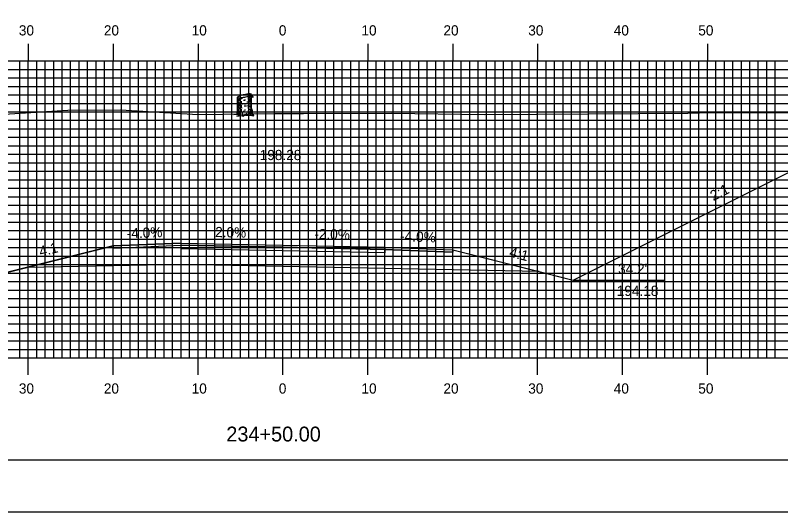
# Model space of a CAD drawing. Extents: x 1800355 to 1800699, y 442591 to 442811.
# Drawn here: x 1800489.5 to 1800579.7, y 442590.5 to 442649 of the extents above; entities that cross this region are included whole.
import ezdxf

# ---------------------------------------------------------------- set-up
doc = ezdxf.new("R2010")
doc.units = 0
for name, color, linetype in [('ANNOTATION', 7, 'Continuous'), ('BORDER', 7, 'Continuous'), ('D_Roadway_Centerline', 7, 'Continuous'), ('D_Roadway_Centerline_Text', 7, 'Continuous'), ('D_Roadway_Edge_Shoulder', 7, 'Continuous'), ('D_Roadway_Edge_TW', 7, 'Continuous'), ('D_Roadway_Pavement', 7, 'Continuous'), ('D_Roadway_SlopeLines', 7, 'Continuous'), ('D_Roadway_SubGrade', 7, 'Continuous'), ('H_V ANNOTATION', 7, 'Continuous'), ('MAJOR', 7, 'Continuous'), ('MINOR', 7, 'Continuous'), ('PDRAIN', 7, 'Continuous'), ('PLOT BOUNDARY', 7, 'Continuous'), ('S_Roadway_Centerline', 7, 'Continuous'), ('S_Trees_Conifer_Pay', 7, 'Continuous')]:
    doc.layers.add(name, color=color, linetype=linetype)

msp = doc.modelspace()

# ---------------------------------------------------------------- linework, layer by layer
at = {"layer": 'BORDER'}
msp.add_lwpolyline([(1800371.436, 442596.665), (1800691.436, 442596.665), (1800691.436, 442806.665), (1800371.436, 442806.665)], close=True, dxfattribs=at)
at = {"layer": 'D_Roadway_Centerline'}
msp.add_lwpolyline([(1800446.785, 442637.108), (1800448.035, 442637.032), (1800449.285, 442636.8), (1800450.535, 442636.41), (1800451.785, 442635.864), (1800486.862, 442618.325), (1800490.862, 442619.325), (1800501.036, 442621.869), (1800509.036, 442622.189), (1800521.036, 442621.949), (1800533.036, 442621.709), (1800541.036, 442621.389), (1800551.21, 442618.845), (1800555.21, 442617.845), (1800591.968, 442636.224), (1800593.218, 442636.77), (1800594.468, 442637.156), (1800595.718, 442637.383), (1800596.968, 442637.451)], dxfattribs=at)
at = {"layer": 'D_Roadway_Edge_Shoulder'}
for points in [[(1800509.036, 442622.189), (1800501.036, 442621.869), (1800501.036, 442621.619), (1800509.036, 442621.939)], [(1800533.036, 442621.709), (1800541.036, 442621.389), (1800541.036, 442621.139), (1800533.036, 442621.459)]]:
    msp.add_lwpolyline(points, close=True, dxfattribs=at)
at = {"layer": 'D_Roadway_Edge_TW'}
msp.add_lwpolyline([(1800509.036, 442621.939), (1800509.036, 442622.189), (1800521.036, 442621.949), (1800533.036, 442621.709), (1800533.036, 442621.459), (1800521.036, 442621.699)], close=True, dxfattribs=at)
at = {"layer": 'D_Roadway_Pavement'}
msp.add_lwpolyline([(1800509.036, 442621.522), (1800509.036, 442621.939), (1800521.036, 442621.699), (1800533.036, 442621.459), (1800533.036, 442621.042), (1800521.036, 442621.282)], close=True, dxfattribs=at)
at = {"layer": 'D_Roadway_SlopeLines'}
for points in [[(1800555.21, 442617.845), (1800591.968, 442636.224), (1800593.218, 442636.77), (1800594.468, 442637.156), (1800595.718, 442637.383), (1800596.968, 442637.451)], [(1800501.036, 442621.869), (1800486.862, 442618.325)], [(1800541.036, 442621.389), (1800555.21, 442617.845)]]:
    msp.add_lwpolyline(points, dxfattribs=at)
at = {"layer": 'D_Roadway_SubGrade'}
msp.add_lwpolyline([(1800509.036, 442619.689), (1800490.862, 442619.325), (1800501.036, 442621.869), (1800501.036, 442621.619), (1800509.036, 442621.939), (1800521.036, 442621.699), (1800533.036, 442621.459), (1800541.036, 442621.139), (1800541.036, 442621.389), (1800551.21, 442618.845), (1800533.036, 442619.209), (1800521.036, 442619.449)], close=True, dxfattribs=at)
at = {"layer": 'MAJOR'}
for p, q in [((1800491.036, 442645.669), (1800491.036, 442643.665)), ((1800501.036, 442645.669), (1800501.036, 442643.665)), ((1800511.036, 442645.669), (1800511.036, 442643.665)), ((1800521.036, 442645.669), (1800521.036, 442643.665)), ((1800531.036, 442645.669), (1800531.036, 442643.665)), ((1800541.036, 442645.669), (1800541.036, 442643.665)), ((1800551.036, 442645.669), (1800551.036, 442643.665)), ((1800561.036, 442645.669), (1800561.036, 442643.665)), ((1800571.036, 442645.669), (1800571.036, 442643.665)), ((1800381.036, 442643.665), (1800661.036, 442643.665)), ((1800381.036, 442643.665), (1800661.036, 442643.665)), ((1800491.036, 442608.665), (1800491.036, 442643.665)), ((1800501.036, 442608.665), (1800501.036, 442643.665)), ((1800511.036, 442608.665), (1800511.036, 442643.665)), ((1800521.036, 442608.665), (1800521.036, 442643.665)), ((1800531.036, 442608.665), (1800531.036, 442643.665)), ((1800541.036, 442608.665), (1800541.036, 442643.665)), ((1800551.036, 442608.665), (1800551.036, 442643.665)), ((1800561.036, 442608.665), (1800561.036, 442643.665)), ((1800571.036, 442608.665), (1800571.036, 442643.665)), ((1800381.036, 442638.665), (1800661.036, 442638.665)), ((1800381.036, 442633.665), (1800661.036, 442633.665)), ((1800381.036, 442628.665), (1800661.036, 442628.665)), ((1800381.036, 442623.665), (1800661.036, 442623.665)), ((1800381.036, 442618.665), (1800661.036, 442618.665)), ((1800381.036, 442613.665), (1800661.036, 442613.665)), ((1800381.036, 442608.665), (1800661.036, 442608.665)), ((1800381.036, 442608.665), (1800661.036, 442608.665)), ((1800491.036, 442606.661), (1800491.036, 442608.665)), ((1800501.036, 442606.661), (1800501.036, 442608.665)), ((1800511.036, 442606.661), (1800511.036, 442608.665)), ((1800521.036, 442606.661), (1800521.036, 442608.665)), ((1800531.036, 442606.661), (1800531.036, 442608.665)), ((1800541.036, 442606.661), (1800541.036, 442608.665)), ((1800551.036, 442606.661), (1800551.036, 442608.665)), ((1800561.036, 442606.661), (1800561.036, 442608.665)), ((1800571.036, 442606.661), (1800571.036, 442608.665))]:
    msp.add_line(p, q, dxfattribs=at)
at = {"layer": 'MINOR'}
for p, q in [((1800490.036, 442608.665), (1800490.036, 442643.665)), ((1800492.036, 442608.665), (1800492.036, 442643.665)), ((1800493.036, 442608.665), (1800493.036, 442643.665)), ((1800494.036, 442608.665), (1800494.036, 442643.665)), ((1800495.036, 442608.665), (1800495.036, 442643.665)), ((1800496.036, 442608.665), (1800496.036, 442643.665)), ((1800497.036, 442608.665), (1800497.036, 442643.665)), ((1800498.036, 442608.665), (1800498.036, 442643.665)), ((1800499.036, 442608.665), (1800499.036, 442643.665)), ((1800500.036, 442608.665), (1800500.036, 442643.665)), ((1800502.036, 442608.665), (1800502.036, 442643.665)), ((1800503.036, 442608.665), (1800503.036, 442643.665)), ((1800504.036, 442608.665), (1800504.036, 442643.665)), ((1800505.036, 442608.665), (1800505.036, 442643.665)), ((1800506.036, 442608.665), (1800506.036, 442643.665)), ((1800507.036, 442608.665), (1800507.036, 442643.665)), ((1800508.036, 442608.665), (1800508.036, 442643.665)), ((1800509.036, 442608.665), (1800509.036, 442643.665)), ((1800510.036, 442608.665), (1800510.036, 442643.665)), ((1800512.036, 442608.665), (1800512.036, 442643.665)), ((1800513.036, 442608.665), (1800513.036, 442643.665)), ((1800514.036, 442608.665), (1800514.036, 442643.665)), ((1800515.036, 442608.665), (1800515.036, 442643.665)), ((1800516.036, 442608.665), (1800516.036, 442643.665)), ((1800517.036, 442608.665), (1800517.036, 442643.665)), ((1800518.036, 442608.665), (1800518.036, 442643.665)), ((1800519.036, 442608.665), (1800519.036, 442643.665)), ((1800520.036, 442608.665), (1800520.036, 442643.665)), ((1800522.036, 442608.665), (1800522.036, 442643.665)), ((1800523.036, 442608.665), (1800523.036, 442643.665)), ((1800524.036, 442608.665), (1800524.036, 442643.665)), ((1800525.036, 442608.665), (1800525.036, 442643.665)), ((1800526.036, 442608.665), (1800526.036, 442643.665)), ((1800527.036, 442608.665), (1800527.036, 442643.665)), ((1800528.036, 442608.665), (1800528.036, 442643.665)), ((1800529.036, 442608.665), (1800529.036, 442643.665)), ((1800530.036, 442608.665), (1800530.036, 442643.665)), ((1800532.036, 442608.665), (1800532.036, 442643.665)), ((1800533.036, 442608.665), (1800533.036, 442643.665)), ((1800534.036, 442608.665), (1800534.036, 442643.665)), ((1800535.036, 442608.665), (1800535.036, 442643.665)), ((1800536.036, 442608.665), (1800536.036, 442643.665)), ((1800537.036, 442608.665), (1800537.036, 442643.665)), ((1800538.036, 442608.665), (1800538.036, 442643.665)), ((1800539.036, 442608.665), (1800539.036, 442643.665)), ((1800540.036, 442608.665), (1800540.036, 442643.665)), ((1800542.036, 442608.665), (1800542.036, 442643.665)), ((1800543.036, 442608.665), (1800543.036, 442643.665)), ((1800544.036, 442608.665), (1800544.036, 442643.665)), ((1800545.036, 442608.665), (1800545.036, 442643.665)), ((1800546.036, 442608.665), (1800546.036, 442643.665)), ((1800547.036, 442608.665), (1800547.036, 442643.665)), ((1800548.036, 442608.665), (1800548.036, 442643.665)), ((1800549.036, 442608.665), (1800549.036, 442643.665)), ((1800550.036, 442608.665), (1800550.036, 442643.665)), ((1800552.036, 442608.665), (1800552.036, 442643.665)), ((1800553.036, 442608.665), (1800553.036, 442643.665)), ((1800554.036, 442608.665), (1800554.036, 442643.665)), ((1800555.036, 442608.665), (1800555.036, 442643.665)), ((1800556.036, 442608.665), (1800556.036, 442643.665)), ((1800557.036, 442608.665), (1800557.036, 442643.665)), ((1800558.036, 442608.665), (1800558.036, 442643.665)), ((1800559.036, 442608.665), (1800559.036, 442643.665)), ((1800560.036, 442608.665), (1800560.036, 442643.665)), ((1800562.036, 442608.665), (1800562.036, 442643.665)), ((1800563.036, 442608.665), (1800563.036, 442643.665)), ((1800564.036, 442608.665), (1800564.036, 442643.665)), ((1800565.036, 442608.665), (1800565.036, 442643.665)), ((1800566.036, 442608.665), (1800566.036, 442643.665)), ((1800567.036, 442608.665), (1800567.036, 442643.665)), ((1800568.036, 442608.665), (1800568.036, 442643.665)), ((1800569.036, 442608.665), (1800569.036, 442643.665)), ((1800570.036, 442608.665), (1800570.036, 442643.665)), ((1800572.036, 442608.665), (1800572.036, 442643.665)), ((1800573.036, 442608.665), (1800573.036, 442643.665)), ((1800574.036, 442608.665), (1800574.036, 442643.665)), ((1800575.036, 442608.665), (1800575.036, 442643.665)), ((1800576.036, 442608.665), (1800576.036, 442643.665)), ((1800577.036, 442608.665), (1800577.036, 442643.665)), ((1800578.036, 442608.665), (1800578.036, 442643.665)), ((1800579.036, 442608.665), (1800579.036, 442643.665)), ((1800381.036, 442642.665), (1800661.036, 442642.665)), ((1800381.036, 442641.665), (1800661.036, 442641.665)), ((1800381.036, 442640.665), (1800661.036, 442640.665)), ((1800381.036, 442639.665), (1800661.036, 442639.665)), ((1800381.036, 442637.665), (1800661.036, 442637.665)), ((1800381.036, 442636.665), (1800661.036, 442636.665)), ((1800381.036, 442635.665), (1800661.036, 442635.665)), ((1800381.036, 442634.665), (1800661.036, 442634.665)), ((1800381.036, 442632.665), (1800661.036, 442632.665)), ((1800381.036, 442631.665), (1800661.036, 442631.665)), ((1800381.036, 442630.665), (1800661.036, 442630.665)), ((1800381.036, 442629.665), (1800661.036, 442629.665)), ((1800381.036, 442627.665), (1800661.036, 442627.665)), ((1800381.036, 442626.665), (1800661.036, 442626.665)), ((1800381.036, 442625.665), (1800661.036, 442625.665)), ((1800381.036, 442624.665), (1800661.036, 442624.665)), ((1800381.036, 442622.665), (1800661.036, 442622.665)), ((1800381.036, 442621.665), (1800661.036, 442621.665)), ((1800381.036, 442620.665), (1800661.036, 442620.665)), ((1800381.036, 442619.665), (1800661.036, 442619.665)), ((1800381.036, 442617.665), (1800661.036, 442617.665)), ((1800381.036, 442616.665), (1800661.036, 442616.665)), ((1800381.036, 442615.665), (1800661.036, 442615.665)), ((1800381.036, 442614.665), (1800661.036, 442614.665)), ((1800381.036, 442612.665), (1800661.036, 442612.665)), ((1800381.036, 442611.665), (1800661.036, 442611.665)), ((1800381.036, 442610.665), (1800661.036, 442610.665)), ((1800381.036, 442609.665), (1800661.036, 442609.665))]:
    msp.add_line(p, q, dxfattribs=at)
at = {"layer": 'PDRAIN'}
msp.add_line((1800555.21, 442617.845), (1800565.981, 442617.845), dxfattribs=at)
at = {"layer": 'PLOT BOUNDARY'}
msp.add_lwpolyline([(1800355.249, 442590.547), (1800695.249, 442590.547), (1800695.249, 442810.547), (1800355.249, 442810.547)], close=True, dxfattribs=at)
at = {"layer": 'S_Roadway_Centerline'}
msp.add_lwpolyline([(1800381.036, 442637.582), (1800384.707, 442637.567), (1800390.588, 442637.59), (1800394.622, 442637.583), (1800399.155, 442637.61), (1800413.826, 442637.413), (1800418.377, 442637.205), (1800435.829, 442637.083), (1800456.918, 442637.131), (1800463.996, 442637.327), (1800472.298, 442637.349), (1800488.199, 442637.398), (1800495.707, 442637.844), (1800501.914, 442637.883), (1800511.044, 442637.357), (1800520.114, 442637.451), (1800523.463, 442637.458), (1800533.833, 442637.493), (1800544.802, 442637.358), (1800557.045, 442637.448), (1800568.724, 442637.522), (1800571.516, 442637.59), (1800590.673, 442637.519)], dxfattribs=at)
at = {"layer": 'S_Trees_Conifer_Pay'}
for p, q in [((1800515.683, 442637.656), (1800515.683, 442639.377)), ((1800515.73, 442639.34), (1800515.73, 442638.869)), ((1800515.788, 442639.329), (1800515.788, 442639.231)), ((1800515.788, 442639.157), (1800515.788, 442638.953)), ((1800515.914, 442639.321), (1800515.914, 442639.089)), ((1800515.914, 442639.048), (1800515.914, 442638.974)), ((1800516.134, 442639.341), (1800516.134, 442639.173)), ((1800516.539, 442639.11), (1800516.539, 442639.015)), ((1800516.929, 442639.383), (1800516.929, 442639.184)), ((1800516.929, 442639.126), (1800516.929, 442639.038)), ((1800517.158, 442639.58), (1800517.158, 442639.356)), ((1800517.158, 442639.268), (1800517.158, 442639.221)), ((1800517.215, 442639.085), (1800517.164, 442639.025)), ((1800517.275, 442639.641), (1800517.275, 442639.478)), ((1800517.275, 442639.41), (1800517.275, 442639.282)), ((1800517.275, 442639.095), (1800517.275, 442638.759)), ((1800517.347, 442638.066), (1800517.347, 442639.713)), ((1800515.73, 442638.805), (1800515.73, 442638.496)), ((1800515.73, 442638.449), (1800515.73, 442637.957)), ((1800515.788, 442638.895), (1800515.788, 442638.696)), ((1800515.788, 442638.648), (1800515.788, 442638.312)), ((1800515.788, 442638.259), (1800515.788, 442638.124)), ((1800515.914, 442638.57), (1800515.914, 442638.432)), ((1800515.914, 442638.16), (1800515.914, 442638.019)), ((1800516.134, 442638.937), (1800516.134, 442638.7)), ((1800516.134, 442638.455), (1800516.134, 442638.303)), ((1800516.134, 442638.259), (1800516.134, 442638.086)), ((1800516.539, 442638.496), (1800516.539, 442638.422)), ((1800516.539, 442638.397), (1800516.539, 442638.249)), ((1800516.929, 442638.69), (1800516.929, 442638.585)), ((1800516.929, 442638.218), (1800516.929, 442638.072)), ((1800517.158, 442638.885), (1800517.158, 442638.753)), ((1800517.158, 442638.643), (1800517.158, 442638.533)), ((1800517.158, 442638.397), (1800517.158, 442638.255)), ((1800517.275, 442638.723), (1800517.275, 442638.56)), ((1800517.275, 442638.513), (1800517.275, 442638.296)), ((1800517.275, 442638.265), (1800517.275, 442638.191)), ((1800517.275, 442638.15), (1800517.275, 442637.977)), ((1800515.73, 442637.903), (1800515.73, 442637.656)), ((1800515.788, 442638.024), (1800515.788, 442637.646)), ((1800515.914, 442637.757), (1800515.914, 442637.662)), ((1800515.914, 442637.263), (1800516.076, 442637.326)), ((1800516.134, 442637.809), (1800516.134, 442637.656)), ((1800516.351, 442637.198), (1800516.225, 442637.263)), ((1800516.539, 442637.957), (1800516.539, 442637.804)), ((1800516.929, 442637.839), (1800516.929, 442637.751)), ((1800517.158, 442638.028), (1800517.158, 442637.856))]:
    msp.add_line(p, q, dxfattribs=at)
for points in [[(1800517.13, 442639.173), (1800517.099, 442639.089), (1800517.095, 442639.021), (1800517.126, 442638.958)], [(1800517.164, 442639.211), (1800517.2, 442639.137), (1800517.248, 442639.194), (1800517.305, 442639.262), (1800517.398, 442639.456), (1800517.462, 442639.503), (1800517.493, 442639.509)], [(1800517.178, 442638.958), (1800517.215, 442639.085), (1800517.279, 442639.2), (1800517.309, 442639.268), (1800517.378, 442639.414)], [(1800517.393, 442639.444), (1800517.468, 442639.452), (1800517.54, 442639.353)], [(1800515.862, 442638.683), (1800515.856, 442638.778), (1800515.899, 442638.755), (1800515.899, 442638.661)], [(1800517.001, 442638.284), (1800517.013, 442638.208), (1800517.061, 442638.218), (1800517.048, 442638.385)], [(1800517.347, 442638.066), (1800517.398, 442637.804), (1800517.414, 442637.53), (1800517.472, 442637.405), (1800517.608, 442637.374), (1800517.378, 442637.337), (1800517.378, 442637.337), (1800517.384, 442637.29), (1800517.631, 442637.195), (1800517.357, 442637.211), (1800517.001, 442637.232), (1800516.679, 442637.221), (1800516.686, 442637.304), (1800516.538, 442637.221), (1800516.351, 442637.198), (1800516.375, 442637.131), (1800516.107, 442637.174), (1800515.887, 442637.147), (1800515.594, 442637.164), (1800515.883, 442637.221), (1800515.914, 442637.263), (1800515.751, 442637.32), (1800515.514, 442637.331), (1800515.273, 442637.331), (1800515.615, 442637.389), (1800515.656, 442637.469), (1800515.683, 442637.656)], [(1800515.731, 442637.608), (1800515.71, 442637.53), (1800515.689, 442637.436)], [(1800515.809, 442637.588), (1800515.815, 442637.473), (1800515.761, 442637.384), (1800515.751, 442637.32)], [(1800515.971, 442637.615), (1800515.971, 442637.483), (1800515.883, 442637.384)], [(1800516.198, 442637.374), (1800516.265, 442637.469), (1800516.292, 442637.608)], [(1800516.686, 442637.304), (1800516.76, 442637.446), (1800516.77, 442637.547)], [(1800516.937, 442637.673), (1800516.947, 442637.547), (1800517.021, 442637.503)], [(1800517.215, 442637.284), (1800517.2, 442637.421), (1800517.126, 442637.551)], [(1800517.174, 442637.778), (1800517.248, 442637.673), (1800517.252, 442637.5), (1800517.378, 442637.337)], [(1800517.273, 442637.923), (1800517.279, 442637.778), (1800517.326, 442637.709), (1800517.336, 442637.51)]]:
    msp.add_lwpolyline(points, dxfattribs=at)
for centre, radius, start, end in [((1800515.715, 442639.199), 0.0334, 163.94846, 180), ((1800515.715, 442639.199), 0.0334, 180, 196.05154), ((1800515.714, 442639.376), 0.0314, 156.51582, 169.2194), ((1800515.709, 442639.377), 0.0264, 169.2194, 180.03145), ((1800515.705, 442639.377), 0.0226, 180.03145, 191.7194), ((1800515.705, 442639.377), 0.0226, 191.7194, 203.40735), ((1800515.725, 442639.202), 0.0441, 196.05154, 210), ((1800515.734, 442639.368), 0.0527, 146.7194, 156.51582), ((1800515.709, 442639.379), 0.0264, 203.40735, 214.2194), ((1800515.713, 442639.381), 0.0314, 214.2194, 226.92298), ((1800515.741, 442639.211), 0.0624, 210, 228.74941), ((1800515.758, 442639.352), 0.0817, 132.38868, 146.7194), ((1800515.728, 442639.397), 0.0527, 226.92298, 236.7194), ((1800515.744, 442639.421), 0.0817, 236.7194, 251.05013), ((1800515.814, 442639.294), 0.172, 228.74941, 240), ((1800515.872, 442639.227), 0.251, 124.2194, 132.38868), ((1800515.798, 442639.581), 0.251, 251.05013, 259.2194), ((1800516.013, 442639.639), 0.571, 240, 240.33672), ((1800516.182, 442638.771), 0.802, 108.05939, 124.2194), ((1800515.901, 442640.122), 0.802, 259.2194, 275.37941), ((1800516.013, 442639.639), 0.571, 246.85973, 257.98457), ((1800517.539, 442634.61), 5.179, 101.7194, 108.05939), ((1800515.491, 442644.48), 5.179, 275.37941, 281.7194), ((1800516.515, 442643.389), 4.124, 264.6955, 266.73309), ((1800516.514, 442643.157), 4.124, 268.07512, 270), ((1800517.539, 442634.61), 5.179, 95.37941, 101.7194), ((1800516.514, 442643.157), 4.124, 270, 270.35814), ((1800515.491, 442644.48), 5.179, 281.7194, 288.05939), ((1800516.514, 442643.157), 4.124, 275.78493, 277.05584), ((1800516.515, 442643.389), 4.124, 276.23804, 278.1032), ((1800517.128, 442638.968), 0.802, 79.2194, 95.37941), ((1800517.016, 442639.872), 0.571, 278.1032, 284.36665), ((1800516.848, 442640.319), 0.802, 288.05939, 304.2194), ((1800517.016, 442640.026), 0.571, 284.43166, 292.41325), ((1800517.016, 442639.872), 0.571, 297.0237, 300), ((1800517.231, 442639.509), 0.251, 71.05013, 79.2194), ((1800517.158, 442639.863), 0.251, 304.2194, 312.38868), ((1800517.215, 442639.681), 0.172, 300, 311.25059), ((1800517.215, 442639.527), 0.172, 300, 311.25059), ((1800517.286, 442639.669), 0.0817, 56.7194, 71.05013), ((1800517.272, 442639.738), 0.0817, 312.38868, 326.7194), ((1800517.288, 442639.599), 0.0624, 311.25059, 330), ((1800517.288, 442639.444), 0.0624, 311.25059, 330), ((1800517.302, 442639.693), 0.0527, 46.92298, 56.7194), ((1800517.317, 442639.709), 0.0314, 34.2194, 46.92298), ((1800517.296, 442639.722), 0.0527, 326.7194, 336.51582), ((1800517.303, 442639.589), 0.0441, 330, 343.94846), ((1800517.303, 442639.435), 0.0441, 330, 343.94846), ((1800517.321, 442639.711), 0.0264, 23.40735, 34.2194), ((1800517.316, 442639.714), 0.0314, 336.51582, 349.2194), ((1800517.324, 442639.713), 0.0226, 11.7194, 23.40735), ((1800517.324, 442639.713), 0.0226, 0.03145, 11.7194), ((1800517.32, 442639.713), 0.0264, 349.2194, 0.03145), ((1800517.314, 442639.587), 0.0334, 343.94846, 354.21506), ((1800517.314, 442639.432), 0.0334, 343.94846, 354.21506), ((1800515.715, 442638.752), 0.0334, 163.94846, 180), ((1800515.715, 442638.752), 0.0334, 180, 196.05154), ((1800515.715, 442638.542), 0.0334, 163.94846, 180), ((1800515.715, 442638.542), 0.0334, 180, 196.05154), ((1800515.715, 442638.306), 0.0334, 163.94846, 180), ((1800515.715, 442638.306), 0.0334, 180, 196.05154), ((1800515.715, 442638.108), 0.0334, 163.94846, 180), ((1800515.725, 442638.755), 0.0441, 196.05154, 210), ((1800515.725, 442638.545), 0.0441, 196.05154, 210), ((1800515.725, 442638.309), 0.0441, 196.05154, 210), ((1800515.741, 442638.764), 0.0624, 210, 228.74941), ((1800515.741, 442638.554), 0.0624, 210, 228.74941), ((1800515.741, 442638.318), 0.0624, 210, 228.74941), ((1800515.814, 442638.847), 0.172, 228.74941, 240), ((1800515.814, 442638.637), 0.172, 228.74941, 240), ((1800515.814, 442638.4), 0.172, 228.74941, 240), ((1800516.013, 442639.192), 0.571, 240, 240.33672), ((1800516.013, 442638.982), 0.571, 240, 246.85973), ((1800516.013, 442638.745), 0.571, 240, 246.85973), ((1800516.014, 442639.428), 0.571, 240, 247.05866), ((1800516.013, 442638.982), 0.571, 259.27072, 261.8968), ((1800516.514, 442642.5), 4.124, 261.8968, 263.14738), ((1800516.514, 442642.71), 4.124, 264.08098, 266.66759), ((1800516.514, 442642.263), 4.124, 264.71603, 266.31934), ((1800516.514, 442642.5), 4.124, 270, 270.35814), ((1800516.514, 442642.5), 4.124, 273.14934, 275.45691), ((1800516.515, 442642.945), 4.124, 273.70524, 275.95043), ((1800516.514, 442642.71), 4.124, 277.61247, 278.1032), ((1800517.014, 442639.192), 0.571, 278.1032, 286.92962), ((1800517.016, 442639.428), 0.571, 284.44928, 297.04285), ((1800517.014, 442638.745), 0.571, 285.39827, 297.18959), ((1800517.014, 442639.192), 0.571, 297.18959, 300), ((1800517.014, 442638.982), 0.571, 297.18959, 300), ((1800517.214, 442638.847), 0.172, 300, 311.25059), ((1800517.214, 442638.637), 0.172, 300, 311.25059), ((1800517.286, 442638.764), 0.0624, 311.25059, 330), ((1800517.286, 442638.554), 0.0624, 311.25059, 330), ((1800517.302, 442638.755), 0.0441, 330, 343.94846), ((1800517.302, 442638.545), 0.0441, 330, 343.94846), ((1800517.302, 442638.111), 0.0441, 330, 343.94846), ((1800517.312, 442638.752), 0.0334, 343.94846, 354.21506), ((1800517.312, 442638.542), 0.0334, 343.94846, 354.21506), ((1800517.312, 442638.108), 0.0334, 343.94846, 354.21506), ((1800517.313, 442638.988), 0.0334, 343.94846, 354.21506), ((1800515.715, 442637.912), 0.0334, 163.94846, 180), ((1800515.715, 442637.912), 0.0334, 180, 196.05154), ((1800515.715, 442637.692), 0.0334, 163.94846, 180), ((1800515.715, 442637.692), 0.0334, 180, 196.05154), ((1800515.725, 442637.915), 0.0441, 196.05154, 210), ((1800515.725, 442637.695), 0.0441, 196.05154, 210), ((1800515.741, 442637.924), 0.0624, 210, 228.74941), ((1800515.741, 442637.704), 0.0624, 210, 228.74941), ((1800515.814, 442638.007), 0.172, 228.74941, 240), ((1800515.814, 442637.787), 0.172, 228.74941, 240), ((1800516.002, 442638.554), 0.571, 241.23686, 248.02677), ((1800516.013, 442638.352), 0.571, 240, 246.85973), ((1800516.013, 442638.132), 0.571, 240, 244.53138), ((1800516.514, 442641.649), 4.124, 262.44379, 263.51202), ((1800516.514, 442642.065), 4.124, 263.49906, 265.83975), ((1800516.514, 442641.87), 4.124, 267.81166, 270), ((1800516.514, 442641.87), 4.124, 270, 270.13279), ((1800516.514, 442641.87), 4.124, 275.78493, 276.78961), ((1800516.514, 442641.649), 4.124, 277.36842, 278.1032), ((1800517.014, 442638.132), 0.571, 278.1032, 281.63703), ((1800517.014, 442638.352), 0.571, 288.50673, 297.27208), ((1800517.014, 442638.548), 0.571, 289.29072, 300), ((1800517.214, 442638.203), 0.172, 300, 311.25059), ((1800517.214, 442637.787), 0.172, 300, 311.25059), ((1800517.286, 442638.12), 0.0624, 311.25059, 330), ((1800517.286, 442637.704), 0.0624, 311.25059, 330), ((1800517.302, 442637.695), 0.0441, 330, 343.94846), ((1800517.312, 442637.692), 0.0334, 343.94846, 354.21506)]:
    msp.add_arc(centre, radius, start, end, dxfattribs=at)

# ---------------------------------------------------------------- texts
at = {"layer": 'ANNOTATION'}
for s, rotation, p in [('2:1', 26.56505, (1800571.734, 442627.143)), ('-4.0%', 2.29061, (1800502.668, 442622.736)), ('2.0%', 358.85424, (1800513.043, 442622.909)), ('-2.0%', 358.85424, (1800524.722, 442622.675)), ('-4.0%', 357.70939, (1800534.828, 442622.439)), ('4:1', 14.03624, (1800492.485, 442620.593)), ('4:1', 345.96376, (1800547.629, 442620.602))]:
    msp.add_text(s, height=1.2, rotation=rotation, dxfattribs=at).set_placement(p)
for s, p in [("34.2'", (1800560.52, 442618.571)), ('194.18', (1800560.36, 442615.971))]:
    msp.add_text(s, height=1.2, dxfattribs=at).set_placement(p)
at = {"layer": 'D_Roadway_Centerline'}
for s, p in [('C', (1800521.031, 442621.949)), ('L', (1800521.036, 442621.941))]:
    msp.add_text(s, height=0.0146, dxfattribs=at).set_placement(p)
at = {"layer": 'D_Roadway_Centerline_Text'}
msp.add_text('198.28', height=1.2, dxfattribs=at).set_placement((1800518.302, 442631.979))
at = {"layer": 'H_V ANNOTATION'}
for s, height, p in [('30', 1.2, (1800489.934, 442646.665)), ('20', 1.2, (1800499.944, 442646.665)), ('10', 1.2, (1800510.287, 442646.665)), ('0', 1.2, (1800520.554, 442646.665)), ('10', 1.2, (1800530.287, 442646.665)), ('20', 1.2, (1800539.944, 442646.665)), ('30', 1.2, (1800549.934, 442646.665)), ('40', 1.2, (1800560.008, 442646.665)), ('50', 1.2, (1800569.965, 442646.665)), ('30', 1.2, (1800489.934, 442604.465)), ('20', 1.2, (1800499.944, 442604.465)), ('10', 1.2, (1800510.287, 442604.465)), ('0', 1.2, (1800520.554, 442604.465)), ('10', 1.2, (1800530.287, 442604.465)), ('20', 1.2, (1800539.944, 442604.465)), ('30', 1.2, (1800549.934, 442604.465)), ('40', 1.2, (1800560.008, 442604.465)), ('50', 1.2, (1800569.965, 442604.465)), ('234+50.00', 1.75, (1800514.372, 442598.821))]:
    msp.add_text(s, height=height, dxfattribs=at).set_placement(p)

doc.saveas('drawing.dxf')
